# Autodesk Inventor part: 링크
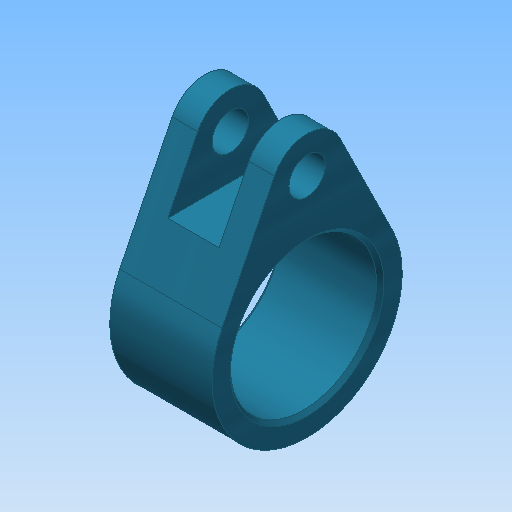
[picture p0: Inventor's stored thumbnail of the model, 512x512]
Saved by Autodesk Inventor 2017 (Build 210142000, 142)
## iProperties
Created: 2016-02
Part Number: 링크
Material: 강철, 연강
Document SubType Name: Modeling
Designer: test
Density: 1 g/cm^3
Appearance: 터키옥색
Author: test
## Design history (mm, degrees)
sketch "스케치1"
  geometry: L1 (20.222, 4.479)-(5.778, 11.645); L2 (20.222, -4.479)-(5.778, -11.645); A1 r 13 centre (0, 0) between (5.778, 11.645) and (5.778, -11.645); A2 r 5 centre (18, 0) between (20.222, -4.479) and (20.222, 4.479); 1 further point
  constraints: 4 end point, 4 point on circle, 4 tangent, 2 centre point, 1 coincident, 1 horizontal alignment
  dimensions: "d0" = 18 distance of point (0, 0) A2.centre; "d1" = 13 radius of A1; "d2" = 5 radius of A2
extrude "돌출1" new body sketch "스케치1" stored distance "d3" = 14; taper "d4" = 0 deg
sketch "스케치2"
  geometry: C1 r 10 at (0, 0); 1 further point
  constraints: 1 centre point, 1 coincident
  dimensions: "d5" = 20 diameter of C1
extrude "돌출2" cut sketch "스케치2" stored distance "d6" = 14; taper "d7" = 0 deg
sketch "스케치3"
  geometry: C1 r 2.5 at (18, 0); A1 r 5 centre (18, 0) between (20.222, -4.479) and (20.222, 4.479) reference; 1 further point
  constraints: 1 centre point, 1 coincident
  dimensions: "d8" = 5 diameter of C1
extrude "돌출3" cut sketch "스케치3" stored distance "d9" = 14; taper "d10" = 0 deg
sketch "스케치4"
  geometry: L1 (20.222, -4.479)-(5.778, -11.645) reference; L2 (5.778, 11.645)-(20.222, 4.479) reference; L3 (12, 8.558)-(12, -8.558); C1 r 2.5 at (18, 0) reference; C2 r 10 at (0, 0) reference; A1 r 13 centre (0, 0) between (5.778, 11.645) and (5.778, -11.645) reference; A2 r 5 centre (18, 0) between (20.222, -4.479) and (20.222, 4.479) reference; 1 further point
  constraints: 2 end point, 2 point on line, 1 vertical
  dimensions: "d11" = 12 distance from line of L3 point (0, 0)
extrude "돌출4" cut sketch "스케치4" stored distance "d12" = 7; taper "d13" = 0 deg
chamfer "모따기1" distance "d14" = 0.5; stored, may be unused: second distance "d15" = 2, angle "d16" = 45 deg
node "솔리드1"
node "절단 모서리 투영1"
